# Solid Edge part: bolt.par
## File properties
Author: Ionut
Template: Normal.par
Last saved by: Ionut
Revision: 3
Application: Solid Edge
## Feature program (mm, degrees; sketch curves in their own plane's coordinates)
sketch for "unnamed Protrusion 1" plane through (0, 0, 0) normal (0, -1, 0) x-axis (1, 0, 0)
  circle centre (0, 0) radius 1.5
extrude "unnamed Protrusion 1" add finite 6 along +normal
sketch for "unnamed Protrusion 2" plane through (0, -6, 0) normal (0, -1, 0) x-axis (1, 0, 0)
  circle centre (0, 0) radius 2
extrude "unnamed Protrusion 2" add finite 1 along +normal
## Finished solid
Body 1: solid body, 5 faces, 4 edges, 0 vertices.
  Faces by surface: plane 3, cylinder 2
  Edges by curve: circle 4
Bounding box of the edges (mm): 4.000 x 7.000 x 4.000, from (-2, -7, -2) to (2, 0, 2).
Cylindrical faces by radius (mm): R1.5 x1, R2 x1
Planar faces by outward normal: +y 2, -y 1
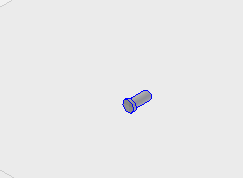
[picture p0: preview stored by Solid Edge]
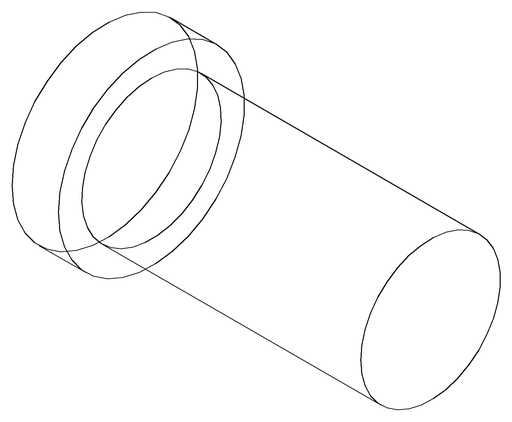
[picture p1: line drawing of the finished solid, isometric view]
